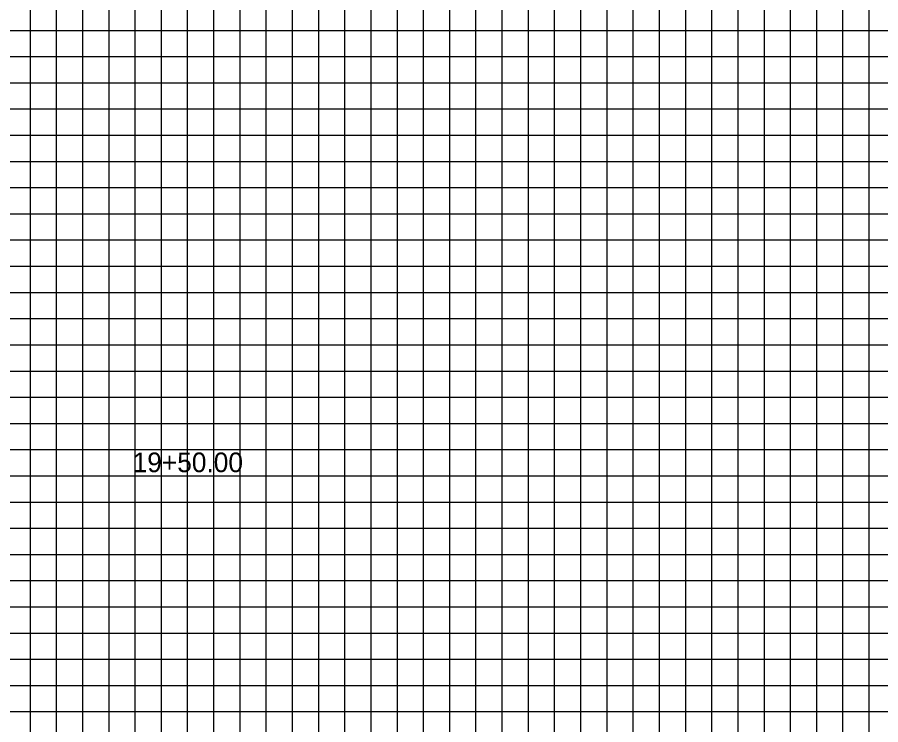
# Model space of a CAD drawing. Extents: x 967 to 1326, y 964 to 2864.
# Drawn here: x 1147 to 1212.9, y 1579 to 1633 of the extents above; entities that cross this region are included whole.
import ezdxf

# ---------------------------------------------------------------- set-up
doc = ezdxf.new("R2010")
doc.units = 0
for name, color, linetype in [('Default', 7, 'Continuous'), ('RD_EX_RW', 7, 'Continuous'), ('RD_SHT_ShtClip', 7, 'Continuous')]:
    doc.layers.add(name, color=color, linetype=linetype)

msp = doc.modelspace()

# ---------------------------------------------------------------- linework, layer by layer
at = {"layer": 'RD_EX_RW'}
for p, q in [((1150, 1560), (1150, 1730)), ((1160, 1560), (1160, 1730)), ((1170, 1560), (1170, 1730)), ((1180, 1560), (1180, 1730)), ((1190, 1560), (1190, 1730)), ((1200, 1560), (1200, 1730)), ((1210, 1560), (1210, 1730)), ((1000, 1630), (1320, 1630)), ((1000, 1620), (1320, 1620)), ((1000, 1610), (1320, 1610)), ((1000, 1600), (1320, 1600)), ((1000, 1590), (1320, 1590)), ((1000, 1580), (1320, 1580))]:
    msp.add_line(p, q, dxfattribs=at)
at = {"layer": 'RD_SHT_ShtClip'}
for p, q in [((1148, 1560), (1148, 1730)), ((1152, 1560), (1152, 1730)), ((1154, 1560), (1154, 1730)), ((1156, 1560), (1156, 1730)), ((1158, 1560), (1158, 1730)), ((1162, 1560), (1162, 1730)), ((1164, 1560), (1164, 1730)), ((1166, 1560), (1166, 1730)), ((1168, 1560), (1168, 1730)), ((1172, 1560), (1172, 1730)), ((1174, 1560), (1174, 1730)), ((1176, 1560), (1176, 1730)), ((1178, 1560), (1178, 1730)), ((1182, 1560), (1182, 1730)), ((1184, 1560), (1184, 1730)), ((1186, 1560), (1186, 1730)), ((1188, 1560), (1188, 1730)), ((1192, 1560), (1192, 1730)), ((1194, 1560), (1194, 1730)), ((1196, 1560), (1196, 1730)), ((1198, 1560), (1198, 1730)), ((1202, 1560), (1202, 1730)), ((1204, 1560), (1204, 1730)), ((1206, 1560), (1206, 1730)), ((1208, 1560), (1208, 1730)), ((1212, 1560), (1212, 1730)), ((1000, 1632), (1320, 1632)), ((1000, 1628), (1320, 1628)), ((1000, 1626), (1320, 1626)), ((1000, 1624), (1320, 1624)), ((1000, 1622), (1320, 1622)), ((1000, 1618), (1320, 1618)), ((1000, 1616), (1320, 1616)), ((1000, 1614), (1320, 1614)), ((1000, 1612), (1320, 1612)), ((1000, 1608), (1320, 1608)), ((1000, 1606), (1320, 1606)), ((1000, 1604), (1320, 1604)), ((1000, 1602), (1320, 1602)), ((1000, 1598), (1320, 1598)), ((1000, 1596), (1320, 1596)), ((1000, 1594), (1320, 1594)), ((1000, 1592), (1320, 1592)), ((1000, 1588), (1320, 1588)), ((1000, 1586), (1320, 1586)), ((1000, 1584), (1320, 1584)), ((1000, 1582), (1320, 1582))]:
    msp.add_line(p, q, dxfattribs=at)

# ---------------------------------------------------------------- texts
at = {"layer": 'Default'}
msp.add_text('19+50.00', height=1.5, dxfattribs=at).set_placement((1155.801, 1598.278))

doc.saveas('drawing.dxf')
